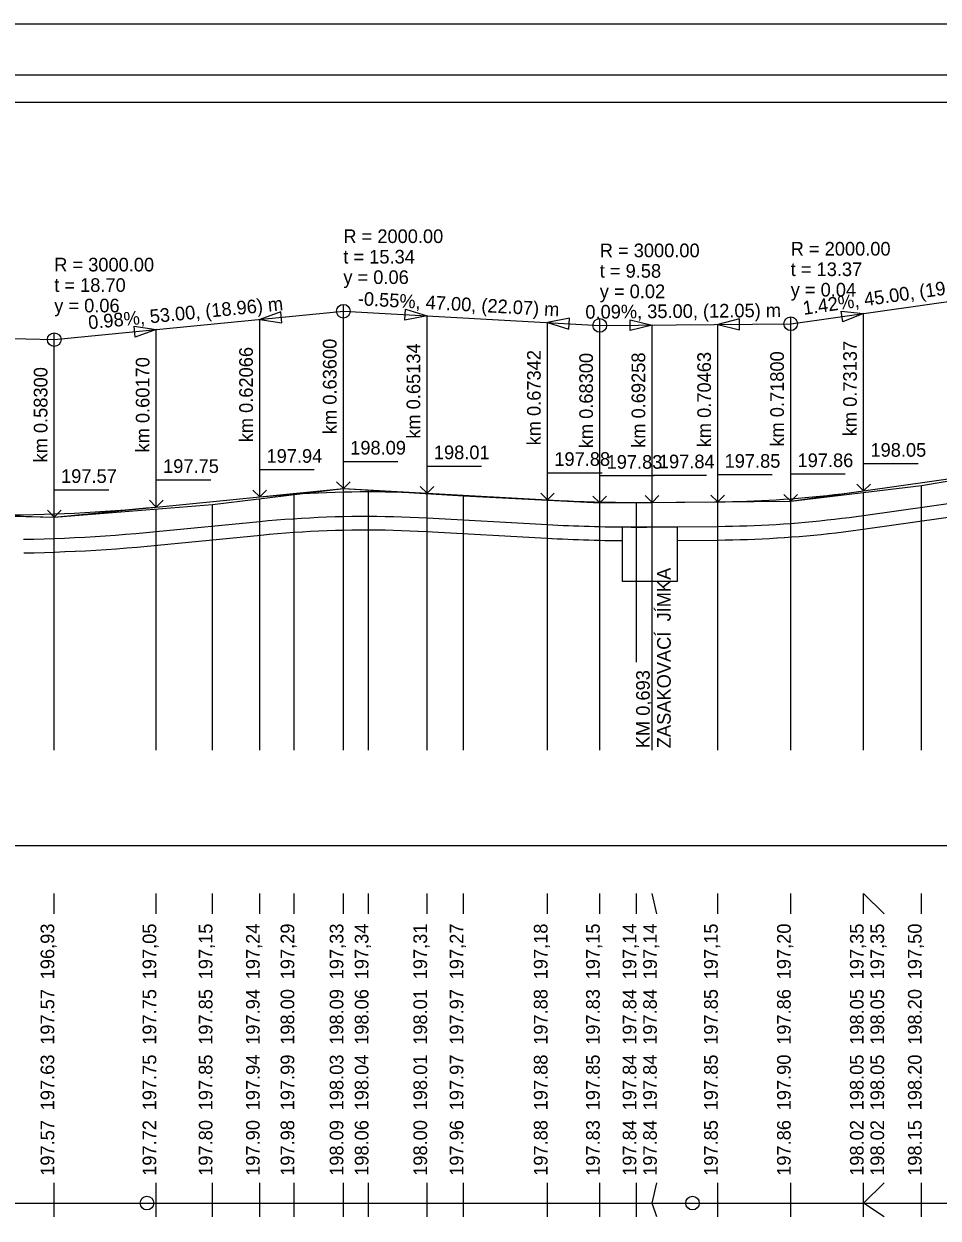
# Model space of a CAD drawing. Extents: x -51 to 53, y -74 to 15.
# Drawn here: x 19.3 to 36.06, y -6.73 to 15.15 of the extents above; entities that cross this region are included whole.
import ezdxf

# ---------------------------------------------------------------- set-up
doc = ezdxf.new("R2010")
doc.units = 0
for name, color, linetype in [('Implicitní', 7, 'Continuous'), ('KONSTRUKCE_L', 7, 'Continuous'), ('KOTY_L', 7, 'Continuous'), ('KOTY_N', 7, 'Continuous'), ('KOTY_S', 7, 'Continuous'), ('KOTY_T', 7, 'Continuous'), ('KOTY_VP', 7, 'Continuous'), ('Nová vrstva (0)', 7, 'Continuous'), ('PR_SKLON_L', 7, 'Continuous'), ('ROVINA_L', 7, 'Continuous'), ('ROVINA_O', 7, 'Continuous'), ('SKLON_POMERY', 7, 'Continuous'), ('TABULKY_L', 7, 'Continuous'), ('TEREN_L', 7, 'Continuous'), ('V_POLYGON', 7, 'Continuous'), ('V_POLYGON_ZO', 7, 'Continuous')]:
    doc.layers.add(name, color=color, linetype=linetype)

msp = doc.modelspace()

# ---------------------------------------------------------------- linework, layer by layer
at = {"layer": 'Implicitní'}
msp.add_lwpolyline([(-51.392, 15.154), (53.079, 15.154), (53.079, -14.546), (-51.392, -14.546)], close=True, dxfattribs=at)
at = {"layer": 'KONSTRUKCE_L'}
for p, q in [((34.697, 6.149), (36.683, 6.431)), ((25.007, 6.126), (25.16, 6.13)), ((25.16, 6.13), (25.313, 6.133)), ((25.313, 6.133), (25.467, 6.134)), ((25.467, 6.134), (25.62, 6.135)), ((25.62, 6.135), (25.774, 6.134)), ((25.774, 6.134), (25.927, 6.132)), ((25.927, 6.132), (26.081, 6.128)), ((26.081, 6.128), (26.234, 6.124)), ((34.429, 6.113), (34.563, 6.13)), ((34.563, 6.13), (34.697, 6.149)), ((21.73, 5.852), (23.626, 6.038)), ((23.626, 6.038), (23.779, 6.053)), ((23.779, 6.053), (23.933, 6.066)), ((23.933, 6.066), (24.086, 6.078)), ((24.086, 6.078), (24.239, 6.089)), ((24.239, 6.089), (24.393, 6.099)), ((24.393, 6.099), (24.546, 6.107)), ((24.546, 6.107), (24.7, 6.115)), ((24.7, 6.115), (24.853, 6.121)), ((24.853, 6.121), (25.007, 6.126)), ((26.234, 6.124), (26.387, 6.119)), ((26.387, 6.119), (26.541, 6.112)), ((26.541, 6.112), (26.694, 6.104)), ((26.694, 6.104), (28.902, 5.982)), ((28.902, 5.982), (28.997, 5.977)), ((28.997, 5.977), (29.093, 5.972)), ((29.093, 5.972), (29.189, 5.967)), ((29.189, 5.967), (29.285, 5.963)), ((29.285, 5.963), (29.381, 5.959)), ((29.381, 5.959), (29.477, 5.956)), ((29.477, 5.956), (29.572, 5.952)), ((29.572, 5.952), (29.668, 5.949)), ((29.668, 5.949), (29.764, 5.947)), ((29.764, 5.947), (29.86, 5.944)), ((29.86, 5.944), (29.956, 5.942)), ((29.956, 5.942), (30.052, 5.94)), ((30.052, 5.94), (30.148, 5.939)), ((30.148, 5.939), (30.243, 5.938)), ((30.243, 5.938), (30.339, 5.937)), ((30.339, 5.937), (30.435, 5.936)), ((30.435, 5.936), (30.531, 5.936)), ((30.531, 5.936), (30.627, 5.936)), ((30.627, 5.936), (30.723, 5.936)), ((30.723, 5.936), (30.818, 5.937)), ((30.818, 5.937), (32.023, 5.947)), ((32.023, 5.947), (32.157, 5.949)), ((32.157, 5.949), (32.291, 5.951)), ((32.291, 5.951), (32.424, 5.955)), ((32.424, 5.955), (32.558, 5.959)), ((32.558, 5.959), (32.692, 5.964)), ((32.692, 5.964), (32.825, 5.97)), ((32.825, 5.97), (32.959, 5.977)), ((32.959, 5.977), (33.093, 5.985)), ((33.093, 5.985), (33.226, 5.994)), ((33.226, 5.994), (33.36, 6.003)), ((33.36, 6.003), (33.494, 6.014)), ((33.494, 6.014), (33.627, 6.025)), ((33.627, 6.025), (33.761, 6.038)), ((33.761, 6.038), (33.895, 6.051)), ((33.895, 6.051), (34.028, 6.065)), ((34.028, 6.065), (34.162, 6.08)), ((34.162, 6.08), (34.296, 6.096)), ((34.296, 6.096), (34.429, 6.113)), ((19.299, 5.712), (19.486, 5.716)), ((19.486, 5.716), (19.673, 5.721)), ((19.673, 5.721), (19.86, 5.727)), ((19.86, 5.727), (20.047, 5.734)), ((20.047, 5.734), (20.234, 5.743)), ((20.234, 5.743), (20.421, 5.752)), ((20.421, 5.752), (20.608, 5.763)), ((20.608, 5.763), (20.795, 5.775)), ((20.795, 5.775), (20.982, 5.788)), ((20.982, 5.788), (21.169, 5.803)), ((21.169, 5.803), (21.356, 5.818)), ((21.356, 5.818), (21.543, 5.835)), ((21.543, 5.835), (21.73, 5.852))]:
    msp.add_line(p, q, dxfattribs=at)
at = {"layer": 'KOTY_L'}
for p, q in [((25.16, 1.849), (25.16, 6.639)), ((25.62, 1.849), (25.62, 6.612)), ((34.697, 1.849), (34.697, 6.57)), ((34.697, 1.849), (34.697, 6.57)), ((35.76, 1.849), (35.76, 6.699)), ((22.76, 1.849), (22.76, 6.349)), ((23.626, 1.849), (23.626, 6.453)), ((24.26, 1.849), (24.26, 6.53)), ((26.694, 1.849), (26.694, 6.548)), ((27.36, 1.849), (27.36, 6.509)), ((28.902, 1.849), (28.902, 6.429)), ((29.86, 1.849), (29.86, 6.379)), ((30.531, 3.463), (30.531, 6.385)), ((30.818, 1.849), (30.818, 6.387)), ((32.023, 1.849), (32.023, 6.397)), ((33.36, 1.849), (33.36, 6.409)), ((21.73, 1.849), (21.73, 6.267)), ((19.86, 1.849), (19.86, 6.119)), ((19.86, -1.151), (19.86, -0.776)), ((21.73, -1.151), (21.73, -0.776)), ((22.76, -1.151), (22.76, -0.776)), ((23.626, -1.151), (23.626, -0.776)), ((24.26, -1.151), (24.26, -0.776)), ((25.16, -1.151), (25.16, -0.776)), ((25.62, -1.151), (25.62, -0.776)), ((26.694, -1.151), (26.694, -0.776)), ((27.36, -1.151), (27.36, -0.776)), ((28.902, -1.151), (28.902, -0.776)), ((29.86, -1.151), (29.86, -0.776)), ((30.531, -1.151), (30.531, -0.776)), ((30.906, -1.151), (30.818, -0.776)), ((32.023, -1.151), (32.023, -0.776)), ((33.36, -1.151), (33.36, -0.776)), ((34.697, -1.151), (34.697, -0.776)), ((35.072, -1.151), (34.697, -0.776)), ((35.76, -1.151), (35.76, -0.776)), ((19.86, -4.751), (19.86, -4.751)), ((21.73, -4.751), (21.73, -4.751)), ((22.76, -4.751), (22.76, -4.751)), ((23.626, -4.751), (23.626, -4.751)), ((24.26, -4.751), (24.26, -4.751)), ((25.16, -4.751), (25.16, -4.751)), ((25.62, -4.751), (25.62, -4.751)), ((26.694, -4.751), (26.694, -4.751)), ((27.36, -4.751), (27.36, -4.751)), ((28.902, -4.751), (28.902, -4.751)), ((29.86, -4.751), (29.86, -4.751)), ((30.531, -4.751), (30.531, -4.751)), ((30.906, -4.751), (30.906, -4.751)), ((32.023, -4.751), (32.023, -4.751)), ((33.36, -4.751), (33.36, -4.751)), ((34.697, -4.751), (34.697, -4.751)), ((35.072, -4.751), (35.072, -4.751)), ((35.76, -4.751), (35.76, -4.751)), ((19.86, -6.451), (19.86, -6.076)), ((21.73, -6.451), (21.73, -6.076)), ((22.76, -6.451), (22.76, -6.076)), ((23.626, -6.451), (23.626, -6.076)), ((24.26, -6.451), (24.26, -6.076)), ((25.16, -6.451), (25.16, -6.076)), ((25.62, -6.451), (25.62, -6.076)), ((26.694, -6.451), (26.694, -6.076)), ((27.36, -6.451), (27.36, -6.076)), ((28.902, -6.451), (28.902, -6.076)), ((29.86, -6.451), (29.86, -6.076)), ((30.531, -6.451), (30.531, -6.076)), ((30.818, -6.451), (30.906, -6.076)), ((32.023, -6.451), (32.023, -6.076)), ((33.36, -6.451), (33.36, -6.076)), ((34.697, -6.451), (34.697, -6.076)), ((34.697, -6.451), (35.072, -6.076)), ((35.76, -6.451), (35.76, -6.076))]:
    msp.add_line(p, q, dxfattribs=at)
at = {"layer": 'KOTY_S'}
for p, q in [((19.86, -6.701), (19.86, -6.451)), ((21.73, -6.701), (21.73, -6.451)), ((22.76, -6.701), (22.76, -6.451)), ((23.626, -6.701), (23.626, -6.451)), ((24.26, -6.701), (24.26, -6.451)), ((25.16, -6.701), (25.16, -6.451)), ((25.62, -6.701), (25.62, -6.451)), ((26.694, -6.701), (26.694, -6.451)), ((27.36, -6.701), (27.36, -6.451)), ((28.902, -6.701), (28.902, -6.451)), ((29.86, -6.701), (29.86, -6.451)), ((30.531, -6.701), (30.531, -6.451)), ((30.906, -6.701), (30.818, -6.451)), ((32.023, -6.701), (32.023, -6.451)), ((33.36, -6.701), (33.36, -6.451)), ((34.697, -6.701), (34.697, -6.451)), ((35.072, -6.701), (34.697, -6.451)), ((35.76, -6.701), (35.76, -6.451))]:
    msp.add_line(p, q, dxfattribs=at)
at = {"layer": 'Nová vrstva (0)'}
for p, q in [((34.732, 5.901), (36.719, 6.184)), ((21.755, 5.603), (23.65, 5.789)), ((23.649, 5.789), (23.803, 5.804)), ((23.801, 5.804), (23.954, 5.817)), ((23.952, 5.817), (24.106, 5.829)), ((24.104, 5.829), (24.257, 5.84)), ((24.255, 5.84), (24.409, 5.849)), ((24.407, 5.849), (24.56, 5.858)), ((24.558, 5.858), (24.712, 5.865)), ((24.71, 5.865), (24.863, 5.871)), ((24.861, 5.871), (25.015, 5.876)), ((25.013, 5.876), (25.166, 5.88)), ((25.164, 5.88), (25.318, 5.883)), ((25.316, 5.883), (25.469, 5.884)), ((25.467, 5.884), (25.621, 5.885)), ((25.619, 5.885), (25.772, 5.884)), ((25.77, 5.884), (25.924, 5.882)), ((25.922, 5.882), (26.075, 5.879)), ((26.073, 5.879), (26.227, 5.874)), ((26.225, 5.874), (26.378, 5.869)), ((26.377, 5.869), (26.53, 5.862)), ((26.528, 5.862), (26.681, 5.854)), ((26.681, 5.854), (28.888, 5.732)), ((28.888, 5.732), (28.984, 5.727)), ((28.985, 5.727), (29.081, 5.722)), ((29.081, 5.722), (29.177, 5.718)), ((29.178, 5.718), (29.274, 5.713)), ((29.275, 5.713), (29.371, 5.709)), ((29.371, 5.709), (29.467, 5.706)), ((29.468, 5.706), (29.564, 5.702)), ((29.565, 5.702), (29.66, 5.699)), ((29.661, 5.699), (29.757, 5.697)), ((29.758, 5.697), (29.854, 5.694)), ((29.855, 5.694), (29.95, 5.692)), ((29.951, 5.692), (30.047, 5.69)), ((30.048, 5.69), (30.144, 5.689)), ((30.144, 5.689), (30.279, 5.687)), ((31.279, 5.691), (32.026, 5.697)), ((32.026, 5.697), (32.16, 5.699)), ((32.162, 5.699), (32.295, 5.701)), ((32.297, 5.702), (32.431, 5.705)), ((32.432, 5.705), (32.566, 5.709)), ((32.568, 5.709), (32.701, 5.714)), ((32.703, 5.715), (32.837, 5.721)), ((32.838, 5.721), (32.972, 5.728)), ((32.974, 5.728), (33.107, 5.736)), ((33.109, 5.736), (33.243, 5.744)), ((33.244, 5.744), (33.378, 5.754)), ((33.38, 5.754), (33.513, 5.765)), ((33.515, 5.765), (33.649, 5.776)), ((33.65, 5.776), (33.784, 5.789)), ((33.786, 5.789), (33.919, 5.802)), ((33.921, 5.802), (34.054, 5.816)), ((34.056, 5.817), (34.19, 5.832)), ((34.191, 5.832), (34.325, 5.848)), ((34.327, 5.848), (34.46, 5.865)), ((34.462, 5.865), (34.596, 5.882)), ((34.597, 5.883), (34.731, 5.901)), ((19.493, 5.466), (19.68, 5.471)), ((19.681, 5.471), (19.868, 5.477)), ((19.87, 5.477), (20.057, 5.485)), ((20.058, 5.485), (20.245, 5.493)), ((20.247, 5.493), (20.434, 5.503)), ((20.435, 5.503), (20.622, 5.514)), ((20.624, 5.514), (20.811, 5.526)), ((20.813, 5.526), (21, 5.539)), ((21.001, 5.539), (21.188, 5.553)), ((21.19, 5.553), (21.377, 5.569)), ((21.378, 5.569), (21.565, 5.586)), ((21.567, 5.586), (21.754, 5.603)), ((19.304, 5.462), (19.491, 5.466))]:
    msp.add_line(p, q, dxfattribs=at)
msp.add_lwpolyline([(30.279, 5.937), (31.279, 5.937), (31.279, 4.937), (30.279, 4.937)], close=True, dxfattribs=at)
at = {"layer": 'PR_SKLON_L'}
msp.add_line((8.36, 0.099), (50.86, 0.099), dxfattribs=at)
at = {"layer": 'ROVINA_L'}
msp.add_line((-38.44, -6.451), (50.86, -6.451), dxfattribs=at)
at = {"layer": 'ROVINA_O'}
for centre in [(21.56, -6.451), (31.56, -6.451)]:
    msp.add_circle(centre, 0.125, dxfattribs=at)
at = {"layer": 'SKLON_POMERY'}
for p, q in [((33.36, 9.659), (37.86, 10.299)), ((19.86, 9.369), (25.16, 9.889)), ((25.16, 9.889), (25.16, 10.014)), ((25.16, 6.639), (25.16, 9.889)), ((25.16, 9.889), (29.86, 9.629)), ((34.697, 6.599), (34.697, 9.849)), ((23.626, 6.488), (23.626, 9.738)), ((26.694, 6.554), (26.694, 9.804)), ((28.902, 6.432), (28.902, 9.682)), ((29.86, 9.629), (29.86, 9.754)), ((29.86, 9.629), (33.36, 9.659)), ((29.86, 6.379), (29.86, 9.629)), ((30.818, 6.387), (30.818, 9.637)), ((32.023, 6.397), (32.023, 9.647)), ((33.36, 9.659), (33.36, 9.784)), ((33.36, 6.409), (33.36, 9.659)), ((13.46, 9.539), (19.86, 9.369)), ((19.86, 9.369), (19.86, 9.494)), ((21.73, 6.302), (21.73, 9.552)), ((19.86, 6.119), (19.86, 9.369))]:
    msp.add_line(p, q, dxfattribs=at)
for points in [[(23.626, 9.738), (24.034, 9.678), (24.014, 9.877), (23.626, 9.738)], [(26.694, 9.804), (26.289, 9.726), (26.3, 9.926), (26.694, 9.804)], [(34.697, 9.849), (34.315, 9.694), (34.286, 9.892), (34.697, 9.849)], [(28.902, 9.682), (29.296, 9.56), (29.307, 9.76), (28.902, 9.682)], [(30.818, 9.637), (30.419, 9.534), (30.418, 9.734), (30.818, 9.637)], [(32.023, 9.647), (32.424, 9.551), (32.423, 9.751), (32.023, 9.647)], [(21.73, 9.552), (21.342, 9.414), (21.322, 9.613), (21.73, 9.552)]]:
    msp.add_lwpolyline(points, close=True, dxfattribs=at)
for points in [[(25.035, 6.764), (25.16, 6.639), (25.285, 6.764), (25.16, 6.639), (25.16, 7.139), (26.16, 7.139)], [(26.569, 6.679), (26.694, 6.554), (26.819, 6.679), (26.694, 6.554), (26.694, 7.054), (27.694, 7.054)], [(34.572, 6.724), (34.697, 6.599), (34.822, 6.724), (34.697, 6.599), (34.697, 7.099), (35.697, 7.099)], [(21.605, 6.427), (21.73, 6.302), (21.855, 6.427), (21.73, 6.302), (21.73, 6.802), (22.73, 6.802)], [(23.501, 6.613), (23.626, 6.488), (23.751, 6.613), (23.626, 6.488), (23.626, 6.988), (24.626, 6.988)], [(28.777, 6.557), (28.902, 6.432), (29.027, 6.557), (28.902, 6.432), (28.902, 6.932), (29.902, 6.932)], [(29.735, 6.504), (29.86, 6.379), (29.985, 6.504), (29.86, 6.379), (29.86, 6.879), (30.86, 6.879)], [(30.693, 6.512), (30.818, 6.387), (30.943, 6.512), (30.818, 6.387), (30.818, 6.887), (31.818, 6.887)], [(31.898, 6.522), (32.023, 6.397), (32.148, 6.522), (32.023, 6.397), (32.023, 6.897), (33.023, 6.897)], [(33.235, 6.534), (33.36, 6.409), (33.485, 6.534), (33.36, 6.409), (33.36, 6.909), (34.36, 6.909)], [(19.735, 6.244), (19.86, 6.119), (19.985, 6.244), (19.86, 6.119), (19.86, 6.619), (20.86, 6.619)]]:
    msp.add_lwpolyline(points, dxfattribs=at)
for centre in [(25.16, 9.889), (29.86, 9.629), (33.36, 9.659), (19.86, 9.369)]:
    msp.add_circle(centre, 0.125, dxfattribs=at)
at = {"layer": 'TABULKY_L'}
for p, q in [((-38.44, 14.218), (50.86, 14.218)), ((-38.44, 13.718), (50.86, 13.718))]:
    msp.add_line(p, q, dxfattribs=at)
at = {"layer": 'TEREN_L'}
for p, q in [((35.76, 6.699), (37.86, 7.049)), ((22.76, 6.349), (25.16, 6.639)), ((25.16, 6.639), (27.36, 6.509)), ((33.36, 6.409), (35.76, 6.699)), ((19.86, 6.119), (22.76, 6.349)), ((27.36, 6.509), (29.86, 6.379)), ((29.86, 6.379), (33.36, 6.409)), ((18.06, 6.159), (19.86, 6.119))]:
    msp.add_line(p, q, dxfattribs=at)
at = {"layer": 'V_POLYGON'}
for p, q in [((34.697, 6.599), (36.683, 6.881)), ((21.73, 6.302), (23.626, 6.488)), ((26.694, 6.554), (28.902, 6.432)), ((30.818, 6.387), (32.023, 6.397))]:
    msp.add_line(p, q, dxfattribs=at)
for points in [[(23.626, 6.488), (23.779, 6.503), (23.933, 6.516), (24.086, 6.528), (24.239, 6.539), (24.393, 6.549), (24.546, 6.557), (24.7, 6.565), (24.853, 6.571), (25.007, 6.576), (25.16, 6.58), (25.313, 6.583), (25.467, 6.584), (25.62, 6.585), (25.774, 6.584), (25.927, 6.582), (26.081, 6.578), (26.234, 6.574), (26.387, 6.569), (26.541, 6.562), (26.694, 6.554)], [(32.023, 6.397), (32.157, 6.399), (32.291, 6.401), (32.424, 6.405), (32.558, 6.409), (32.692, 6.414), (32.825, 6.42), (32.959, 6.427), (33.093, 6.435), (33.226, 6.444), (33.36, 6.453), (33.494, 6.464), (33.627, 6.475), (33.761, 6.488), (33.895, 6.501), (34.028, 6.515), (34.162, 6.53), (34.296, 6.546), (34.429, 6.563), (34.563, 6.58), (34.697, 6.599)], [(28.902, 6.432), (28.997, 6.427), (29.093, 6.422), (29.189, 6.417), (29.285, 6.413), (29.381, 6.409), (29.477, 6.406), (29.572, 6.402), (29.668, 6.399), (29.764, 6.397), (29.86, 6.394), (29.956, 6.392), (30.052, 6.39), (30.148, 6.389), (30.243, 6.388), (30.339, 6.387), (30.435, 6.386), (30.531, 6.386), (30.627, 6.386), (30.723, 6.386), (30.818, 6.387)], [(17.99, 6.168), (18.177, 6.164), (18.364, 6.161), (18.551, 6.159), (18.738, 6.158), (18.925, 6.158), (19.112, 6.16), (19.299, 6.162), (19.486, 6.166), (19.673, 6.171), (19.86, 6.177), (20.047, 6.184), (20.234, 6.193), (20.421, 6.202), (20.608, 6.213), (20.795, 6.225), (20.982, 6.238), (21.169, 6.253), (21.356, 6.268), (21.543, 6.285), (21.73, 6.302)]]:
    msp.add_lwpolyline(points, dxfattribs=at)
at = {"layer": 'V_POLYGON_ZO'}
for p, q in [((23.626, 6.488), (25.16, 6.639)), ((25.16, 6.639), (26.694, 6.554)), ((33.36, 6.409), (34.697, 6.599)), ((28.902, 6.432), (29.86, 6.379)), ((29.86, 6.379), (30.818, 6.387)), ((32.023, 6.397), (33.36, 6.409)), ((17.99, 6.168), (19.86, 6.119)), ((19.86, 6.119), (21.73, 6.302))]:
    msp.add_line(p, q, dxfattribs=at)

# ---------------------------------------------------------------- texts
at = {"layer": 'KOTY_N'}
for s, p in [('197.63', (19.86, -4.751)), ('197.75', (21.73, -4.751)), ('197.85', (22.76, -4.751)), ('197.94', (23.626, -4.751)), ('197.99', (24.26, -4.751)), ('198.03', (25.16, -4.751)), ('198.04', (25.62, -4.751)), ('198.01', (26.694, -4.751)), ('197.97', (27.36, -4.751)), ('197.88', (28.902, -4.751)), ('197.85', (29.86, -4.751)), ('197.84', (30.531, -4.751)), ('197.84', (30.906, -4.751)), ('197.85', (32.023, -4.751)), ('197.90', (33.36, -4.751)), ('198.05', (34.697, -4.751)), ('198.05', (35.072, -4.751)), ('198.20', (35.76, -4.751))]:
    msp.add_text(s, height=0.25, rotation=90, dxfattribs=at).set_placement(p)
at = {"layer": 'KOTY_T'}
for s, p in [('197.57', (19.86, -5.951)), ('197.72', (21.73, -5.951)), ('197.80', (22.76, -5.951)), ('197.90', (23.626, -5.951)), ('197.98', (24.26, -5.951)), ('198.09', (25.16, -5.951)), ('198.06', (25.62, -5.951)), ('198.00', (26.694, -5.951)), ('197.96', (27.36, -5.951)), ('197.88', (28.902, -5.951)), ('197.83', (29.86, -5.951)), ('197.84', (30.531, -5.951)), ('197.84', (30.906, -5.951)), ('197.85', (32.023, -5.951)), ('197.86', (33.36, -5.951)), ('198.02', (34.697, -5.951)), ('198.02', (35.072, -5.951)), ('198.15', (35.76, -5.951))]:
    msp.add_text(s, height=0.25, rotation=90, dxfattribs=at).set_placement(p)
at = {"layer": 'KOTY_VP'}
for s, p in [('197.57', (19.86, -3.551)), ('197.75', (21.73, -3.551)), ('197.85', (22.76, -3.551)), ('197.94', (23.626, -3.551)), ('198.00', (24.26, -3.551)), ('198.09', (25.16, -3.551)), ('198.06', (25.62, -3.551)), ('198.01', (26.694, -3.551)), ('197.97', (27.36, -3.551)), ('197.88', (28.902, -3.551)), ('197.83', (29.86, -3.551)), ('197.84', (30.531, -3.551)), ('197.84', (30.906, -3.551)), ('197.85', (32.023, -3.551)), ('197.86', (33.36, -3.551)), ('198.05', (34.697, -3.551)), ('198.05', (35.072, -3.551)), ('198.20', (35.76, -3.551))]:
    msp.add_text(s, height=0.25, rotation=90, dxfattribs=at).set_placement(p)
at = {"layer": 'Nová vrstva (0)'}
for s, p in [('ZASAKOVACÍ  JÍMKA', (31.161, 1.884)), ('KM 0,693', (30.777, 1.884)), ('196,93', (19.86, -2.351)), ('197,05', (21.73, -2.351)), ('197,15', (22.76, -2.351)), ('197,24', (23.626, -2.351)), ('197,29', (24.26, -2.351)), ('197,33', (25.16, -2.351)), ('197,34', (25.62, -2.351)), ('197,31', (26.694, -2.351)), ('197,27', (27.36, -2.351)), ('197,18', (28.902, -2.351)), ('197,15', (29.86, -2.351)), ('197,14', (30.531, -2.351)), ('197,14', (30.906, -2.351)), ('197,15', (32.023, -2.351)), ('197,20', (33.36, -2.351)), ('197,35', (34.697, -2.351)), ('197,35', (35.072, -2.351)), ('197,50', (35.76, -2.351))]:
    msp.add_text(s, height=0.25, rotation=90, dxfattribs=at).set_placement(p)
at = {"layer": 'SKLON_POMERY'}
for s, p in [('R = 2000.00', (25.16, 11.139)), ('R = 2000.00', (33.36, 10.909)), ('t = 15.34', (25.16, 10.764)), ('R = 3000.00', (29.86, 10.879)), ('R = 3000.00', (19.86, 10.619)), ('t = 9.58', (29.86, 10.504)), ('t = 13.37', (33.36, 10.534)), ('y = 0.06', (25.16, 10.389)), ('t = 18.70', (19.86, 10.244)), ('y = 0.02', (29.86, 10.129)), ('y = 0.04', (33.36, 10.159)), ('y = 0.06', (19.86, 9.869)), ('198.09', (25.285, 7.264)), ('198.05', (34.822, 7.224)), ('197.94', (23.751, 7.113)), ('198.01', (26.819, 7.179)), ('197.88', (29.027, 7.057)), ('197.83', (29.985, 7.004)), ('197.84', (30.943, 7.012)), ('197.85', (32.148, 7.022)), ('197.86', (33.485, 7.034)), ('197.75', (21.855, 6.927)), ('197.57', (19.985, 6.744))]:
    msp.add_text(s, height=0.25, dxfattribs=at).set_placement(p)
for s, rotation, p in [('1.42%, 45.00, (19.87) m', 8.0945, (33.6, 9.822)), ('0.98%, 53.00, (18.96) m', 5.6035, (20.495, 9.558)), ('-0.55%, 47.00, (22.07) m', 356.8337, (25.42, 10)), ('0.09%, 35.00, (12.05) m', 0.4911, (29.597, 9.752)), ('km 0.62066', 90, (23.501, 7.488)), ('km 0.63600', 90, (25.035, 7.639)), ('km 0.65134', 90, (26.569, 7.554)), ('km 0.73137', 90, (34.572, 7.599)), ('km 0.60170', 90, (21.605, 7.302)), ('km 0.67342', 90, (28.777, 7.432)), ('km 0.68300', 90, (29.735, 7.379)), ('km 0.69258', 90, (30.693, 7.387)), ('km 0.70463', 90, (31.898, 7.397)), ('km 0.71800', 90, (33.235, 7.409)), ('km 0.58300', 90, (19.735, 7.119))]:
    msp.add_text(s, height=0.25, rotation=rotation, dxfattribs=at).set_placement(p)

doc.saveas('drawing.dxf')
